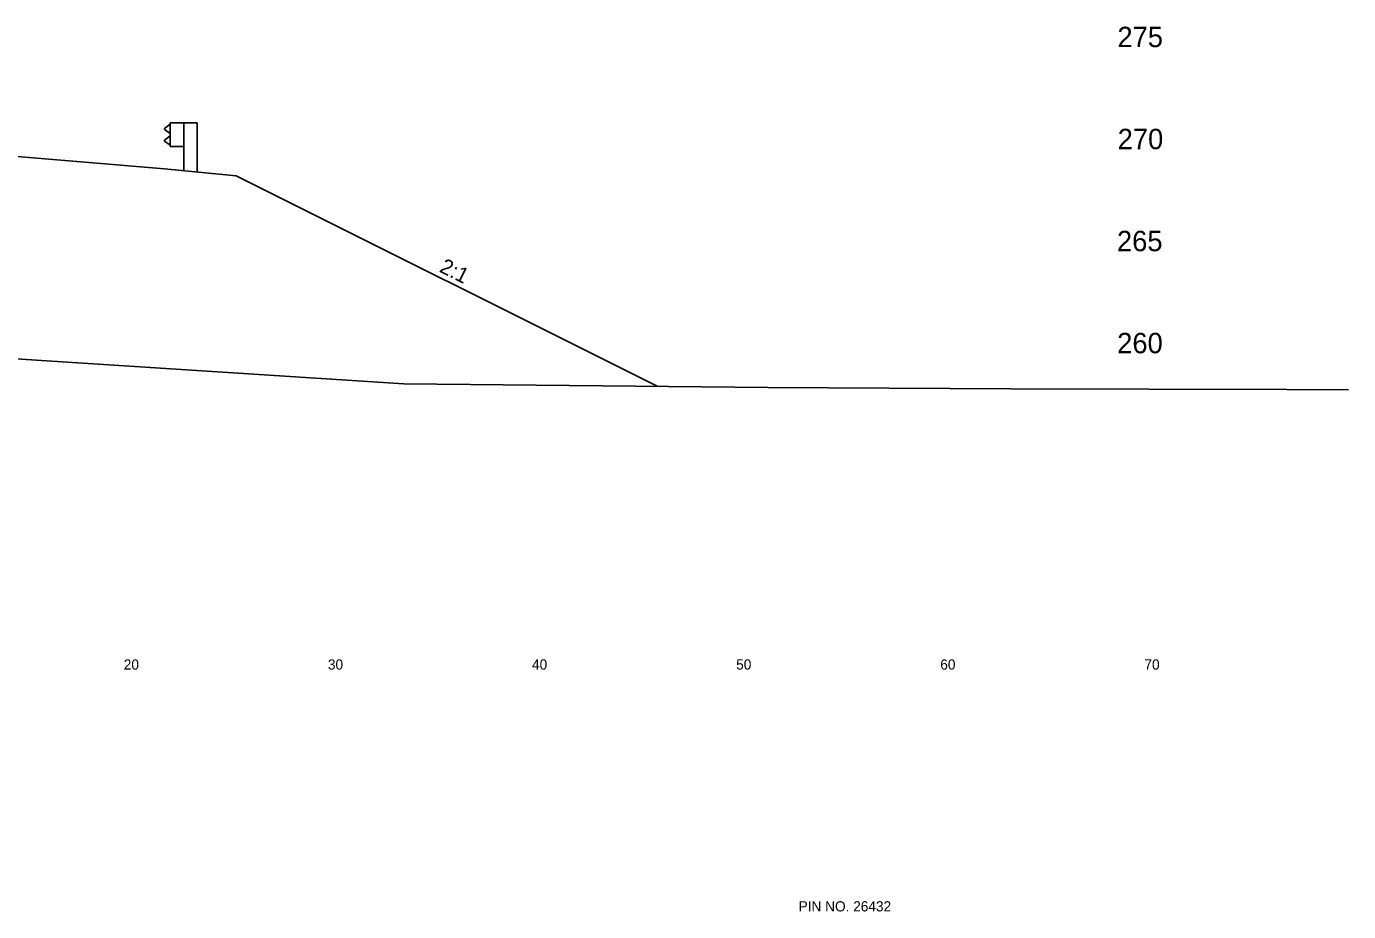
# Model space of a CAD drawing. Extents: x 1000 to 1162, y 999 to 8520.
# Drawn here: x 1095.2 to 1160, y 5242.6 to 5286 of the extents above; entities that cross this region are included whole.
import ezdxf

# ---------------------------------------------------------------- set-up
doc = ezdxf.new("R2010")
doc.units = 0
for name, color, linetype in [('Level 11', 7, 'Continuous'), ('Level 20', 7, 'Continuous'), ('Level 24', 7, 'Continuous'), ('Level 32', 7, 'Continuous'), ('Level 56', 7, 'Continuous'), ('Level 6', 7, 'Continuous'), ('Level 60', 7, 'Continuous'), ('Level 7', 7, 'Continuous')]:
    doc.layers.add(name, color=color, linetype=linetype)

msp = doc.modelspace()

# ---------------------------------------------------------------- linework, layer by layer
at = {"layer": 'Level 24'}
for p, q in [((1102.271, 5281.219), (1102, 5281.019)), ((1102.271, 5280.125), (1102.271, 5281.292)), ((1102.271, 5281.292), (1102.937, 5281.292)), ((1102.937, 5281.292), (1102.937, 5278.949)), ((1102.937, 5281.292), (1103.603, 5281.292)), ((1103.603, 5281.292), (1103.603, 5278.882)), ((1102, 5281.019), (1102, 5280.969)), ((1102, 5280.969), (1102.271, 5280.769)), ((1102, 5280.448), (1102.271, 5280.648)), ((1102, 5280.398), (1102, 5280.448)), ((1102.271, 5280.198), (1102, 5280.398)), ((1102.271, 5280.125), (1102.938, 5280.125))]:
    msp.add_line(p, q, dxfattribs=at)
at = {"layer": 'Level 6'}
for p, q in [((1094, 5279.709), (1102, 5279.042)), ((1102, 5279.042), (1105.5, 5278.692))]:
    msp.add_line(p, q, dxfattribs=at)
at = {"layer": 'Level 60'}
for p, q in [((1080, 5270.666), (1095.964, 5269.646)), ((1095.964, 5269.646), (1113.718, 5268.503)), ((1113.718, 5268.503), (1131.546, 5268.328)), ((1131.546, 5268.328), (1143.454, 5268.252)), ((1143.454, 5268.252), (1156.971, 5268.218)), ((1156.971, 5268.218), (1160, 5268.201))]:
    msp.add_line(p, q, dxfattribs=at)
at = {"layer": 'Level 7'}
msp.add_line((1105.5, 5278.692), (1126.122, 5268.381), dxfattribs=at)

# ---------------------------------------------------------------- texts
at = {"layer": 'Level 11'}
for s, p in [(' 275', (1148.307, 5285)), (' 270', (1148.319, 5280)), (' 265', (1148.284, 5275)), (' 260', (1148.295, 5270))]:
    msp.add_text(s, height=1, dxfattribs=at).set_placement(p)
at = {"layer": 'Level 20'}
msp.add_text('PIN NO. 26432', height=0.5, dxfattribs=at).set_placement((1133.058, 5242.65))
at = {"layer": 'Level 32'}
msp.add_text('2:1', height=0.75, rotation=333.43495, dxfattribs=at).set_placement((1115.416, 5274.014))
at = {"layer": 'Level 56'}
for s, p in [('20', (1100, 5254.5)), ('30', (1110, 5254.5)), ('40', (1120, 5254.5)), ('50', (1130, 5254.5)), ('60', (1140, 5254.5)), ('70', (1150, 5254.5))]:
    msp.add_text(s, height=0.5, dxfattribs=at).set_placement(p)

doc.saveas('drawing.dxf')
